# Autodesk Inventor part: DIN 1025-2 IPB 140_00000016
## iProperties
Created: 2006-02
Part Number: DIN 1025-2 IPB 140_00000016
Material: Default
Document SubType Name: Modeling
Designer: 40664
Manufacturer: Standard
Standards Organization: Custom
Stock Number: DIN 1025-2 IPB 140
Mass: 27320 g
Surface Area: 51344.8 cm^2
Volume: 27320 cm^3
Density: 1 g/cm^3
G_L: 6500.000 mm
G_W: 140.000 mm
G_H: 140.000 mm
AFG_Item: IPB 140
CSToolsMass: 27.0
CSToolsVolume: 27319967.0
CSToolsArea: 51345.0
Author: 40664
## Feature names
1. AFG_Detailed_DIN 1025-2 IPB 140_00000016 [Extrusion]
2. AFG_Simplified_DIN 1025-2 IPB 140_00000016 [Extrusion]
